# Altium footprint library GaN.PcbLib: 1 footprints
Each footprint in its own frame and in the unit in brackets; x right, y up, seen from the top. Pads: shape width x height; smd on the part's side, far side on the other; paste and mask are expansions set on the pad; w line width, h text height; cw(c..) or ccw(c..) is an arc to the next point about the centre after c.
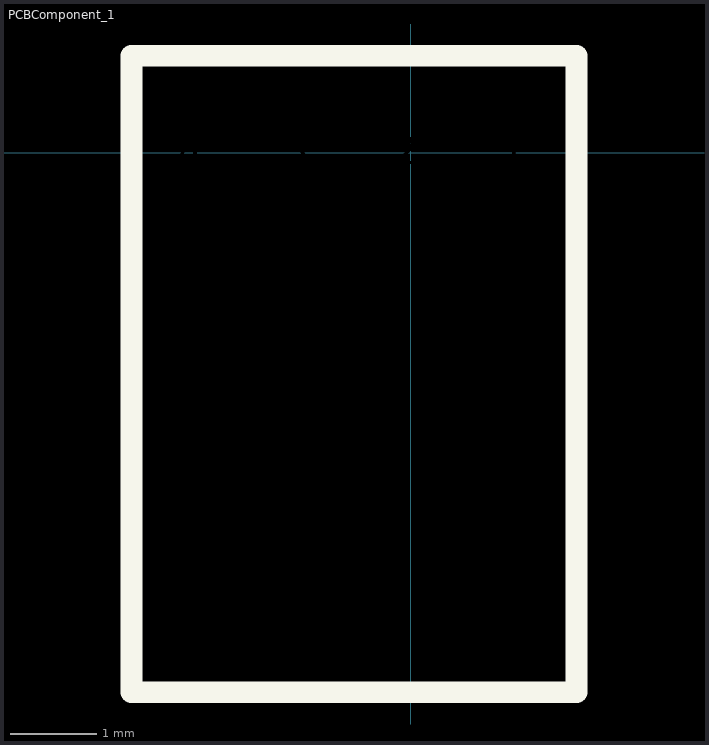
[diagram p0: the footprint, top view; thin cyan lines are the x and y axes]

## PCBComponent_1 [mm]
pads (4):
  rect 0.6x0.775 on Top Solder: 1(1.2,0.025) 2(-0.05,0.025) 3(-1.325,0.025) 4(-2.55,0.025)
Top Overlay:
  lines w0.254: -3.25,-6.275 1.925,-6.275 1.925,1.125 -3.25,1.125 -3.25,-6.275
Top Solder:
  region: -2.875,-0.875 1,-0.875 1.525,-1.4 1.525,-3.15 -2.875,-3.15
  region: -2.863,-4.95 1.538,-4.95 1.538,-5.825 0.937,-5.825 0.937,-5.525 0.262,-5.525 0.262,-5.825 -0.337,-5.825 -0.337,-5.525 -1.012,-5.525 -1.012,-5.825 -1.613,-5.825 -1.613,-5.525 -2.288,-5.525 -2.288,-5.825 -2.863,-5.825
M5 Assembly Top:
  text ".Designator" at -2,-0.7 h1.85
